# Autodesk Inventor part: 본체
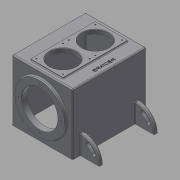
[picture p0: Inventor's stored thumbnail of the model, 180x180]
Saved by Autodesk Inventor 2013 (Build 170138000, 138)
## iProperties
Created: 2016-11
Part Number: 본체
Material: 일반
Document SubType Name: Modeling
Designer: mduedu
Density: 1 g/cm^3
Author: mduedu
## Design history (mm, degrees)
sketch "스케치1"
  geometry: L1 (-80, 0)-(80, 0); L2 (80, 0)-(80, 160); L3 (80, 160)-(-80, 160); L4 (-80, 160)-(-80, 0); 2 further points
  constraints: 8 end point, 2 parallel, 1 coincident, 1 horizontal, 1 midpoint, 1 perpendicular
  dimensions: "d0" = 160 distance of L2.end L3.end; "d2" = 160 distance of L1.end L2.end
extrude "돌출1" new body sketch "스케치1" stored distance "d3" = 194; taper "d4" = 0 deg
sketch "스케치4"
  geometry: L1 (80, 160)-(-80, 160) reference; L2 (-80, 160)-(-80, 0) reference; L3 (80, 0)-(80, 160) reference; L4 (-72, 0)-(-72, 152); L5 (-72, 152)-(72, 152); L6 (72, 152)-(72, 0); L7 (-72, 0)-(72, 0); 4 further points
  constraints: 8 end point, 1 coincident, 1 midpoint, 1 perpendicular
  dimensions: "d23" = 8 distance between parallel lines of L5 L1; "d24" = 8 distance between parallel lines of L3 L6 (= d23); "d25" = 8 distance between parallel lines of L2 L4 (= d23)
extrude "돌출4" cut sketch "스케치4" stored distance "d26" = 178; taper "d27" = 0 deg
fillet "모깎기5" dims "d28" = 3
fillet "모깎기6" dims "d29" = 3
fillet "모깎기7" dims "d30" = 3
fillet "모깎기8" dims "d31" = 3
sketch "스케치5"
  geometry: C1 r 65 at (0, 80); 1 further point
  constraints: 1 centre point, 1 vertical alignment
  dimensions: "d32" = 130 diameter of C1; "d33" = 80 distance of C1.centre point (0, 0)
extrude "돌출5" join sketch "스케치5" distance "d34" = 7; taper "d35" = 0 deg
sketch "스케치6"
  geometry: L1 (0, -3)-(154, -3) reference; L2 (154, 191)-(0, 191) reference; C1 r 35 at (77, 51.5); C2 r 35 at (77, 136.5); 2 further points
  constraints: 2 centre point, 2 vertical alignment, 1 coincident
  dimensions: "d36" = 70 diameter of C1; "d100" = 54.5 distance from line of point (77, 51.5) L1; "d101" = 70 diameter of C2; "d102" = 54.5 distance from line of C2.centre L2
extrude "돌출6" cut sketch "스케치6" stored distance "d37" = 7; taper "d38" = 0 deg
sketch "스케치7"
  geometry: L1 (34.5, 9)-(119.5, 9); L2 (119.5, 9)-(119.5, 179); L3 (119.5, 179)-(34.5, 179); L4 (34.5, 179)-(34.5, 9); L5 (0, -3)-(154, -3) reference; L6 (154, 191)-(0, 191) reference; C1 r 35 at (77, 51.5) reference; C2 r 35 at (77, 136.5) reference; 2 further points
  constraints: 8 end point, 2 parallel, 1 horizontal, 1 midpoint, 1 perpendicular, 1 vertical alignment
  dimensions: "d95" = 170 distance of L3.end L1.start; "d97" = 85 distance of L1.start L1.end; "d98" = 12 distance between parallel lines of L1 L5; "d99" = 12 distance between parallel lines of L3 L6 (derived)
extrude "돌출7" join sketch "스케치7" distance "d41" = 3; taper "d42" = 0 deg
fillet "모깎기9" dims "d43" = 3
fillet "모깎기10" dims "d44" = 2
hole "구멍2" diameter "d47" = 95; stored, may be unused: countersink angle "d51" = 90 deg, drill point angle "d53" = 118 deg; dims "d45" = 10, "d46" = 10, "d48" = 6, "d49" = 14, "d50" = 8, "d52" = 8
chamfer "모따기1" distance "d54" = 1; stored, may be unused: second distance "d55" = 2, angle "d56" = 45 deg
sketch "스케치8"
  geometry: C1 r 65 at (0, 80) reference; C2 r 31.5 at (0, 80); 1 further point
  constraints: 1 centre point, 1 coincident
  dimensions: "d57" = 63 diameter of C2
extrude "돌출8" join sketch "스케치8" distance "d58" = 14; taper "d59" = 0 deg
hole "구멍3" diameter "d62" = 30; stored, may be unused: countersink angle "d66" = 90 deg, drill point angle "d68" = 0 deg; dims "d60" = 10, "d61" = 10, "d63" = 6, "d64" = 47, "d65" = 14, "d67" = 17
fillet "모깎기11" dims "d69" = 3
fillet "모깎기12" dims "d70" = 3
fillet "모깎기13" dims "d71" = 0.5
chamfer "모따기2" distance "d72" = 1; stored, may be unused: second distance "d73" = 2, angle "d74" = 45 deg
fillet "모깎기14" dims "d75" = 3
sketch "스케치9"
  geometry: L1 (157, 0)-(157, 188) reference; L2 (77, 94)-(157, 94); 1 further point
  constraints: 2 end point, 1 midpoint, 1 point on line, 1 other
  dimensions: "d78" = 65 distance of point (142, 94) L2.start
feature "엠보싱1" sketch "스케치9" dims "d79" = 0.5, "d80" = 0
sketch "스케치10"
  geometry: 4 further points
  constraints: 4 other
hole "구멍4" sketch "스케치10" at (0, -55), (55, 0), (-55, 0), (0, 55) diameter "d81" = 3.242; stored, may be unused: countersink angle "d85" = 90 deg, drill point angle "d87" = 120 deg; dims "d82" = 6.6, "d83" = 4, "d84" = 2, "d86" = 8.6
sketch "스케치11"
  geometry: L1 (189, 94)-(-35, 94) reference; 8 further points
  constraints: 4 symmetric about line, 4 other
hole "구멍5" sketch "스케치11" at (42, 86.5), (112, 86.5), (112, 16.5), (42, 16.5), (42, 101.5), (112, 101.5), (112, 171.5), (42, 171.5) diameter "d88" = 3.242; stored, may be unused: countersink angle "d92" = 90 deg, drill point angle "d94" = 120 deg; dims "d89" = 6.6, "d90" = 4, "d91" = 2, "d93" = 8.6
node "작업 평면1"
sketch "스케치12"
  geometry: L1 (80, 157)-(80, 0) reference; L2 (80, 50)-(80, 0); L3 (80, 0)-(130, 0); L4 (80, 0)-(123.301, 25); L5 (80, 0)-(105, 43.301); A1 r 50 centre (80, 0) between (130, 0) and (80, 50); A2 r 40 centre (80, 0) between (120, 0) and (80, 40); A3 r 5 centre (114.641, 20) between (110.311, 17.5) and (118.971, 22.5); A4 r 45 centre (80, 0) between (118.971, 22.5) and (102.5, 38.971); A5 r 35 centre (80, 0) between (110.311, 17.5) and (97.5, 30.311); A6 r 5 centre (100, 34.641) between (102.5, 38.971) and (97.5, 30.311); 1 further point
  constraints: 16 point on circle, 8 end point, 8 point on line, 6 centre point, 4 coincident, 1 collinear, 1 perpendicular, 1 vertical alignment
  dimensions: "d104" = 100 diameter of A1; "d105" = 40 radius of A2; "d106" = 30 deg angle of L3 L4; "d107" = 30 deg angle of L5 L1; "d109" = 10 diameter of A3
extrude "돌출9" join sketch "스케치12" distance "d110" = 10; taper "d111" = 0 deg
extrude "돌출10" cut sketch "스케치12" stored distance "d112" = 10; taper "d113" = 0 deg
fillet "모깎기15" dims "d114" = 2
fillet "모깎기16" dims "d115" = 2
chamfer "모따기3" distance "d116" = 1; stored, may be unused: second distance "d117" = 2, angle "d118" = 45 deg
node "솔리드1"
mirror "대칭4"
